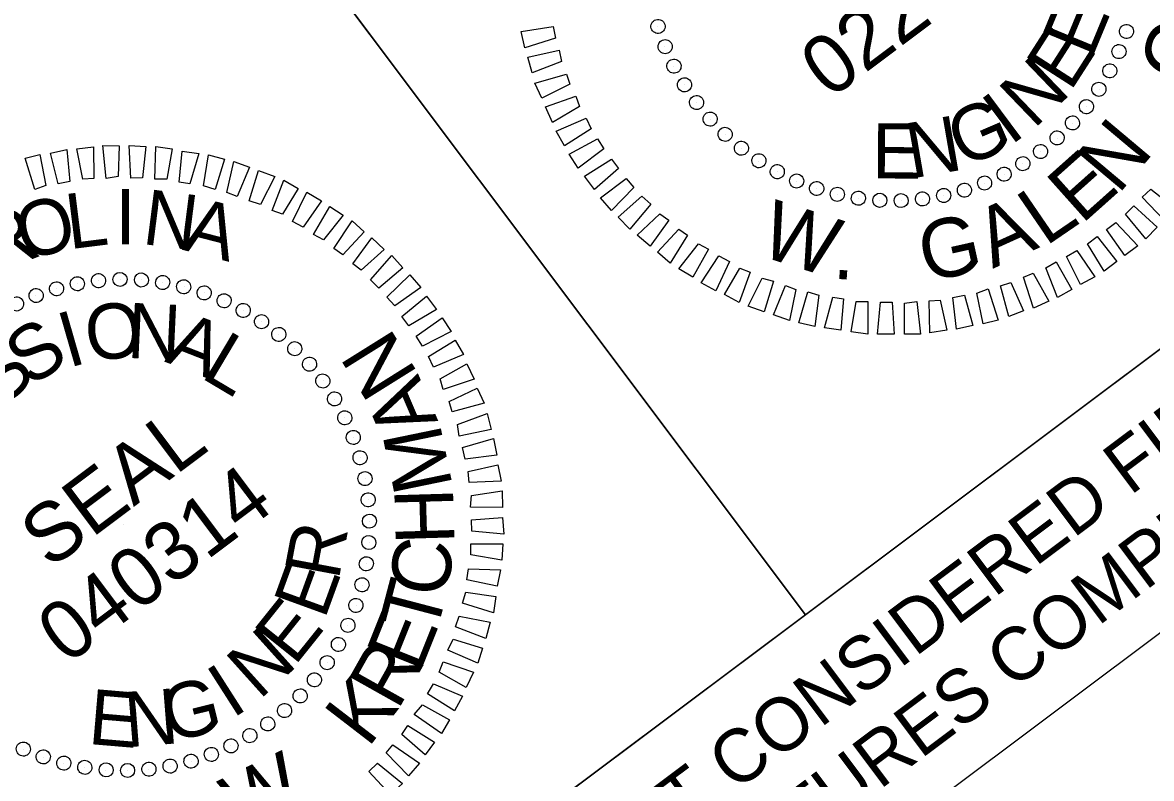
# Model space of a CAD drawing. Extents: x 2186558 to 2188589, y 629855 to 631741.
# Drawn here: x 2187861 to 2187977.7, y 631515.8 to 631594 of the extents above; entities that cross this region are included whole.
import ezdxf

# ---------------------------------------------------------------- set-up
doc = ezdxf.new("R2010")
doc.units = 0
for name, color, linetype in [('Default', 7, 'Continuous'), ('Sheet PE Seal Cell', 7, 'Continuous'), ('Sheet Plan CELL', 7, 'Continuous'), ('Sheet Sticker Exception Certification CELL', 7, 'Continuous')]:
    doc.layers.add(name, color=color, linetype=linetype)

msp = doc.modelspace()

# ---------------------------------------------------------------- linework, layer by layer
at = {"layer": 'Default'}
for p, q in [((2187926.62, 631593.6), (2187926.62, 631593.6)), ((2187975.11, 631593.08), (2187975.11, 631593.08)), ((2187927.37, 631591.5), (2187927.37, 631591.5)), ((2187974.34, 631590.99), (2187974.34, 631590.99)), ((2187928.31, 631589.49), (2187928.31, 631589.49)), ((2187973.37, 631588.99), (2187973.37, 631588.99)), ((2187929.38, 631587.56), (2187929.38, 631587.56)), ((2187972.27, 631587.09), (2187972.27, 631587.09)), ((2187930.63, 631585.72), (2187930.63, 631585.72)), ((2187970.96, 631585.28), (2187970.96, 631585.28)), ((2187932.05, 631584), (2187932.05, 631584)), ((2187969.49, 631583.61), (2187969.49, 631583.61)), ((2187933.6, 631582.44), (2187933.6, 631582.44)), ((2187967.93, 631582.06), (2187967.93, 631582.06)), ((2187935.27, 631580.97), (2187935.27, 631580.97)), ((2187966.21, 631580.65), (2187966.21, 631580.65)), ((2187937.07, 631579.67), (2187937.07, 631579.67)), ((2187938.98, 631578.56), (2187938.98, 631578.56)), ((2187962.45, 631578.33), (2187962.45, 631578.33)), ((2187964.37, 631579.39), (2187964.37, 631579.39)), ((2187940.97, 631577.59), (2187940.97, 631577.59)), ((2187960.43, 631577.38), (2187960.43, 631577.38)), ((2187943.07, 631576.82), (2187943.07, 631576.82)), ((2187945.18, 631576.2), (2187945.18, 631576.2)), ((2187956.2, 631576.11), (2187956.2, 631576.11)), ((2187958.34, 631576.63), (2187958.34, 631576.63)), ((2187947.37, 631575.81), (2187947.37, 631575.81)), ((2187949.58, 631575.57), (2187949.58, 631575.57)), ((2187951.79, 631575.58), (2187951.79, 631575.58)), ((2187954.01, 631575.73), (2187954.01, 631575.73))]:
    msp.add_line(p, q, dxfattribs=at)
for points in [[(2187916.07, 631592.39), (2187912.89, 631591.4), (2187912.52, 631593.08), (2187915.81, 631593.58)], [(2187916.67, 631589.99), (2187913.64, 631588.79), (2187913.19, 631590.41), (2187916.44, 631591.14)], [(2187917.56, 631587.62), (2187914.64, 631586.19), (2187913.92, 631587.74), (2187917.21, 631588.68)], [(2187918.53, 631585.31), (2187915.77, 631583.68), (2187915.02, 631585.27), (2187918.18, 631586.38)], [(2187919.76, 631583), (2187917.01, 631581.26), (2187916.14, 631582.76), (2187919.23, 631584.13)], [(2187921.05, 631580.94), (2187918.42, 631578.96), (2187917.47, 631580.4), (2187920.41, 631581.97)], [(2187922.57, 631578.92), (2187920.09, 631576.74), (2187919.06, 631578.11), (2187921.84, 631579.89)], [(2187924.17, 631576.95), (2187921.85, 631574.57), (2187920.73, 631575.89), (2187923.36, 631577.86)], [(2187925.92, 631575.22), (2187923.74, 631572.64), (2187922.54, 631573.89), (2187924.98, 631576.04)], [(2187977.59, 631576.78), (2187980.2, 631574.75), (2187978.98, 631573.58), (2187976.71, 631575.93)], [(2187975.86, 631575.04), (2187978.26, 631572.85), (2187977.08, 631571.65), (2187974.98, 631574.19)], [(2187927.78, 631573.58), (2187925.84, 631570.86), (2187924.52, 631572.02), (2187926.86, 631574.22)], [(2187929.72, 631572), (2187927.9, 631569.12), (2187926.62, 631570.24), (2187928.8, 631572.64)], [(2187973.99, 631573.32), (2187976.25, 631570.9), (2187974.91, 631569.9), (2187973.02, 631572.59)], [(2187972.05, 631571.86), (2187974.1, 631569.29), (2187972.77, 631568.29), (2187971.07, 631571.13)], [(2187931.87, 631570.57), (2187930.26, 631567.66), (2187928.83, 631568.55), (2187930.83, 631571.12)], [(2187969.96, 631570.42), (2187971.81, 631567.7), (2187970.33, 631566.9), (2187968.9, 631569.81)], [(2187934.04, 631569.29), (2187932.63, 631566.27), (2187931.12, 631567.1), (2187932.96, 631569.88)], [(2187967.8, 631569.25), (2187969.42, 631566.41), (2187967.97, 631565.57), (2187966.74, 631568.64)], [(2187936.19, 631568.19), (2187935.06, 631565.06), (2187933.55, 631565.89), (2187935.13, 631568.59)], [(2187965.44, 631568.1), (2187967.05, 631565.2), (2187965.46, 631564.45), (2187964.43, 631567.67)], [(2187938.59, 631567.26), (2187937.63, 631564.08), (2187935.98, 631564.67), (2187937.41, 631567.58)], [(2187940.89, 631566.39), (2187940.26, 631563.19), (2187938.6, 631563.79), (2187939.83, 631566.8)], [(2187963.13, 631567.13), (2187964.44, 631564.19), (2187962.92, 631563.62), (2187962.06, 631566.77)], [(2187943.3, 631565.8), (2187942.88, 631562.57), (2187941.2, 631562.95), (2187942.16, 631566.14)], [(2187945.85, 631565.43), (2187945.57, 631562.18), (2187943.87, 631562.43), (2187944.72, 631565.6)], [(2187958.35, 631565.82), (2187959.2, 631562.66), (2187957.52, 631562.29), (2187957.15, 631565.56)], [(2187960.79, 631566.45), (2187961.81, 631563.23), (2187960.27, 631562.83), (2187959.6, 631566)], [(2187948.34, 631565.15), (2187948.34, 631561.79), (2187946.63, 631562.03), (2187947.15, 631565.14)], [(2187950.87, 631565.08), (2187951.08, 631561.76), (2187949.35, 631561.79), (2187949.67, 631565.07)], [(2187953.41, 631565.15), (2187953.79, 631561.77), (2187952.13, 631561.79), (2187952.15, 631564.97)], [(2187955.82, 631565.31), (2187956.53, 631562.18), (2187954.75, 631561.92), (2187954.68, 631565.22)]]:
    msp.add_lwpolyline(points, close=True, dxfattribs=at)
for centre, major_axis in [((2187926.66, 631593.6), (-0.698, -0.212)), ((2187975.09, 631593.08), (0.693, -0.227)), ((2187927.4, 631591.51), (-0.676, -0.272)), ((2187974.31, 631591), (0.67, -0.286)), ((2187928.31, 631589.49), (-0.65, -0.33)), ((2187973.36, 631589.01), (0.643, -0.344)), ((2187929.4, 631587.56), (-0.619, -0.385)), ((2187972.23, 631587.1), (0.611, -0.398)), ((2187930.65, 631585.73), (-0.583, -0.438)), ((2187970.94, 631585.3), (0.574, -0.45)), ((2187932.05, 631584.02), (-0.543, -0.487)), ((2187969.5, 631583.62), (0.532, -0.498)), ((2187933.6, 631582.44), (-0.498, -0.532)), ((2187935.28, 631581), (-0.45, -0.574)), ((2187967.91, 631582.07), (0.487, -0.543)), ((2187966.2, 631580.66), (0.438, -0.583)), ((2187937.09, 631579.71), (-0.398, -0.611)), ((2187964.37, 631579.41), (0.385, -0.619)), ((2187938.99, 631578.58), (-0.344, -0.643)), ((2187940.99, 631577.62), (-0.286, -0.67)), ((2187962.44, 631578.32), (0.33, -0.65)), ((2187943.06, 631576.84), (-0.227, -0.693)), ((2187958.33, 631576.67), (0.212, -0.698)), ((2187960.42, 631577.41), (0.272, -0.676)), ((2187945.2, 631576.24), (-0.165, -0.71)), ((2187947.37, 631575.83), (-0.103, -0.722)), ((2187949.58, 631575.62), (-0.04, -0.728)), ((2187951.79, 631575.59), (0.024, -0.729)), ((2187954, 631575.76), (0.087, -0.724)), ((2187956.19, 631576.12), (0.15, -0.713))]:
    msp.add_ellipse(centre, major_axis=major_axis, ratio=0.999708, dxfattribs=at)
at = {"layer": 'Sheet PE Seal Cell'}
for p, q in [((2187866.64, 631567), (2187866.64, 631567)), ((2187868.83, 631567.37), (2187868.83, 631567.37)), ((2187871.05, 631567.45), (2187871.05, 631567.45)), ((2187873.28, 631567.42), (2187873.28, 631567.42)), ((2187875.45, 631567.15), (2187875.45, 631567.15)), ((2187877.67, 631566.73), (2187877.67, 631566.73)), ((2187862.35, 631565.8), (2187862.35, 631565.8)), ((2187864.48, 631566.51), (2187864.48, 631566.51)), ((2187879.74, 631566.07), (2187879.74, 631566.07)), ((2187881.83, 631565.23), (2187881.83, 631565.23)), ((2187883.82, 631564.26), (2187883.82, 631564.26)), ((2187885.69, 631563.12), (2187885.69, 631563.12)), ((2187887.45, 631561.79), (2187887.45, 631561.79)), ((2187889.11, 631560.25), (2187889.11, 631560.25)), ((2187890.66, 631558.69), (2187890.66, 631558.69)), ((2187892.04, 631556.94), (2187892.04, 631556.94)), ((2187893.25, 631555.06), (2187893.25, 631555.06)), ((2187894.28, 631553.11), (2187894.28, 631553.11)), ((2187895.19, 631551.14), (2187895.19, 631551.14)), ((2187895.9, 631549.01), (2187895.9, 631549.01)), ((2187896.38, 631546.84), (2187896.38, 631546.84)), ((2187896.76, 631544.66), (2187896.76, 631544.66)), ((2187896.84, 631542.44), (2187896.84, 631542.44)), ((2187871.44, 631542.05), (2187871.44, 631542.05)), ((2187896.81, 631540.2), (2187896.81, 631540.2)), ((2187896.54, 631538.04), (2187896.54, 631538.04)), ((2187896.11, 631535.82), (2187896.11, 631535.82)), ((2187895.45, 631533.74), (2187895.45, 631533.74)), ((2187894.61, 631531.66), (2187894.61, 631531.66)), ((2187893.64, 631529.66), (2187893.64, 631529.66)), ((2187892.51, 631527.8), (2187892.51, 631527.8)), ((2187891.17, 631526.04), (2187891.17, 631526.04)), ((2187889.64, 631524.37), (2187889.64, 631524.37)), ((2187888.08, 631522.83), (2187888.08, 631522.83)), ((2187886.32, 631521.45), (2187886.32, 631521.45)), ((2187884.45, 631520.23), (2187884.45, 631520.23)), ((2187861.04, 631518.87), (2187861.04, 631518.87)), ((2187882.5, 631519.21), (2187882.5, 631519.21)), ((2187863.13, 631518.03), (2187863.13, 631518.03)), ((2187880.52, 631518.3), (2187880.52, 631518.3)), ((2187865.21, 631517.37), (2187865.21, 631517.37)), ((2187867.42, 631516.95), (2187867.42, 631516.95)), ((2187869.59, 631516.68), (2187869.59, 631516.68)), ((2187871.83, 631516.65), (2187871.83, 631516.65)), ((2187874.04, 631516.73), (2187874.04, 631516.73)), ((2187876.23, 631517.1), (2187876.23, 631517.1)), ((2187878.4, 631517.59), (2187878.4, 631517.59))]:
    msp.add_line(p, q, dxfattribs=at)
for points in [[(2187864.64, 631577.33), (2187863.86, 631580.48), (2187865.55, 631580.86), (2187865.87, 631577.56)], [(2187867.21, 631577.8), (2187866.57, 631580.93), (2187868.3, 631581.15), (2187868.34, 631577.89)], [(2187869.61, 631577.89), (2187869.26, 631581.3), (2187870.95, 631581.24), (2187870.86, 631578.07)], [(2187872.18, 631577.92), (2187872, 631581.27), (2187873.73, 631581.17), (2187873.37, 631577.93)], [(2187874.66, 631577.82), (2187874.74, 631581.17), (2187876.44, 631580.93), (2187875.88, 631577.79)], [(2187877.18, 631577.5), (2187877.49, 631580.71), (2187879.19, 631580.47), (2187878.27, 631577.31)], [(2187862.25, 631576.74), (2187861.26, 631579.99), (2187862.76, 631580.35), (2187863.39, 631577.15)], [(2187879.69, 631577.1), (2187880.19, 631580.32), (2187881.86, 631579.87), (2187880.87, 631576.72)], [(2187882.09, 631576.44), (2187882.8, 631579.63), (2187884.45, 631579.03), (2187883.15, 631576.03)], [(2187884.39, 631575.57), (2187885.38, 631578.71), (2187887.06, 631578.08), (2187885.56, 631575.18)], [(2187886.78, 631574.57), (2187887.98, 631577.69), (2187889.45, 631576.83), (2187887.84, 631574.17)], [(2187888.89, 631573.44), (2187890.37, 631576.45), (2187891.87, 631575.55), (2187889.97, 631572.85)], [(2187891.05, 631572.08), (2187892.73, 631574.99), (2187894.12, 631574.07), (2187892.09, 631571.54)], [(2187893.16, 631570.63), (2187895.05, 631573.5), (2187896.3, 631572.35), (2187894.08, 631569.99)], [(2187895.1, 631569.05), (2187897.08, 631571.73), (2187898.35, 631570.54), (2187895.98, 631568.38)], [(2187896.93, 631567.38), (2187899.13, 631569.92), (2187900.29, 631568.63), (2187897.82, 631566.53)], [(2187898.63, 631565.62), (2187901.02, 631567.92), (2187902.13, 631566.6), (2187899.44, 631564.71)], [(2187900.19, 631563.62), (2187902.73, 631565.72), (2187903.76, 631564.34), (2187900.92, 631562.65)], [(2187901.67, 631561.57), (2187904.36, 631563.46), (2187905.28, 631562.06), (2187902.31, 631560.53)], [(2187902.92, 631559.47), (2187905.7, 631561.17), (2187906.57, 631559.67), (2187903.45, 631558.35)], [(2187904.15, 631557.16), (2187906.9, 631558.72), (2187907.65, 631557.13), (2187904.46, 631556.07)], [(2187905.08, 631554.82), (2187907.98, 631556.18), (2187908.7, 631554.63), (2187905.39, 631553.73)], [(2187905.93, 631552.42), (2187908.99, 631553.58), (2187909.4, 631551.93), (2187906.12, 631551.24)], [(2187906.46, 631550.04), (2187909.67, 631550.99), (2187910, 631549.28), (2187906.72, 631548.84)], [(2187907.04, 631547.57), (2187910.11, 631548.28), (2187910.45, 631546.57), (2187907.14, 631546.43)], [(2187907.38, 631545.09), (2187910.56, 631545.58), (2187910.6, 631543.84), (2187907.28, 631543.88)], [(2187907.38, 631542.56), (2187910.6, 631542.83), (2187910.71, 631541.08), (2187907.43, 631541.4)], [(2187907.32, 631540.11), (2187910.61, 631540.11), (2187910.51, 631538.39), (2187907.3, 631538.96)], [(2187907.06, 631537.51), (2187910.37, 631537.4), (2187910.05, 631535.71), (2187906.9, 631536.38)], [(2187906.78, 631535.09), (2187909.9, 631534.65), (2187909.66, 631532.95), (2187906.44, 631533.95)], [(2187906.11, 631532.62), (2187909.31, 631531.98), (2187908.85, 631530.31), (2187905.73, 631531.52)], [(2187905.48, 631530.25), (2187908.53, 631529.31), (2187908.05, 631527.75), (2187904.95, 631529.1)], [(2187904.46, 631527.9), (2187907.6, 631526.84), (2187906.83, 631525.25), (2187904.05, 631526.84)], [(2187903.45, 631525.62), (2187906.44, 631524.33), (2187905.61, 631522.82), (2187902.83, 631524.59)], [(2187902.3, 631523.44), (2187905.12, 631521.88), (2187904.27, 631520.48), (2187901.47, 631522.43)], [(2187900.8, 631521.3), (2187903.56, 631519.57), (2187902.58, 631518.26), (2187900.17, 631520.38)], [(2187899.25, 631519.31), (2187902.02, 631517.4), (2187900.86, 631516.09), (2187898.56, 631518.47)], [(2187897.65, 631517.41), (2187900.24, 631515.31), (2187898.99, 631514.18), (2187896.76, 631516.56)]]:
    msp.add_lwpolyline(points, close=True, dxfattribs=at)
for centre, major_axis in [((2187866.64, 631566.99), (-0.138, 0.716)), ((2187868.83, 631567.31), (-0.075, 0.725)), ((2187871.05, 631567.44), (-0.011, 0.729)), ((2187873.26, 631567.38), (0.052, 0.727)), ((2187875.46, 631567.12), (0.116, 0.72)), ((2187864.49, 631566.47), (-0.2, 0.701)), ((2187877.63, 631566.68), (0.178, 0.707)), ((2187879.75, 631566.04), (0.239, 0.689)), ((2187860.35, 631564.9), (-0.318, 0.656)), ((2187862.38, 631565.77), (-0.26, 0.681)), ((2187881.81, 631565.23), (0.298, 0.665)), ((2187883.79, 631564.23), (0.355, 0.637)), ((2187885.68, 631563.07), (0.409, 0.604)), ((2187887.46, 631561.75), (0.46, 0.566)), ((2187889.11, 631560.28), (0.507, 0.523)), ((2187890.64, 631558.67), (0.551, 0.477)), ((2187892.01, 631556.93), (0.591, 0.427)), ((2187893.23, 631555.08), (0.626, 0.374)), ((2187894.28, 631553.13), (0.656, 0.318)), ((2187895.16, 631551.1), (0.681, 0.26)), ((2187895.86, 631549), (0.701, 0.2)), ((2187896.37, 631546.84), (0.716, 0.138)), ((2187896.7, 631544.65), (0.725, 0.075)), ((2187896.83, 631542.44), (0.729, 0.011)), ((2187896.76, 631540.23), (0.727, -0.052)), ((2187896.51, 631538.03), (0.72, -0.116)), ((2187896.06, 631535.86), (0.707, -0.178)), ((2187895.43, 631533.73), (0.689, -0.239)), ((2187894.61, 631531.67), (0.665, -0.298)), ((2187893.62, 631529.69), (0.637, -0.355)), ((2187892.46, 631527.81), (0.604, -0.409)), ((2187891.14, 631526.03), (0.566, -0.46)), ((2187889.67, 631524.37), (0.523, -0.507)), ((2187888.06, 631522.85), (0.477, -0.551)), ((2187886.32, 631521.47), (0.427, -0.591)), ((2187882.52, 631519.2), (0.318, -0.656)), ((2187884.47, 631520.26), (0.374, -0.626)), ((2187861.06, 631518.87), (-0.298, -0.665)), ((2187863.12, 631518.06), (-0.239, -0.689)), ((2187880.49, 631518.32), (0.26, -0.681)), ((2187865.24, 631517.42), (-0.178, -0.707)), ((2187867.41, 631516.98), (-0.116, -0.72)), ((2187876.23, 631517.11), (0.138, -0.716)), ((2187878.39, 631517.62), (0.2, -0.701)), ((2187869.61, 631516.72), (-0.052, -0.727)), ((2187871.83, 631516.66), (0.011, -0.729)), ((2187874.04, 631516.79), (0.075, -0.725))]:
    msp.add_ellipse(centre, major_axis=major_axis, ratio=0.999708, dxfattribs=at)
at = {"layer": 'Sheet Plan CELL'}
msp.add_line((2187874.4, 631622.77), (2187941.88, 631532.8), dxfattribs=at)
for points in [[(2187874.4, 631622.77), (2187954.4, 631682.76), (2188021.9, 631592.74), (2187941.9, 631532.75)], [(2187794.35, 631562.75), (2187874.4, 631622.77), (2187941.9, 631532.75), (2187861.84, 631472.76)], [(2187361.55, 629972.91), (2186731.7, 630812.99), (2187771.81, 631592.82), (2187861.84, 631472.76), (2188021.9, 631592.74), (2188561.73, 630872.69)]]:
    msp.add_lwpolyline(points, close=True, dxfattribs=at)
at = {"layer": 'Sheet Sticker Exception Certification CELL'}
for p, q in [((2187861.84, 631472.76), (2188021.89, 631592.75)), ((2187861.84, 631472.76), (2188021.89, 631592.75)), ((2188035.99, 631573.95), (2187875.94, 631453.96)), ((2188035.99, 631573.95), (2187875.94, 631453.96))]:
    msp.add_line(p, q, dxfattribs=at)

# ---------------------------------------------------------------- texts
at = {"layer": 'Default'}
for s, height, rotation, p in [('022000', 6.075, 36.8829, (2187944.42, 631586)), ('E', 5.71, 67.501, (2187971.51, 631590.24)), ('E', 5.71, 57.3041, (2187969.28, 631586.77)), ('C', 6.07, 73.1407, (2187982.13, 631587.31)), ('N', 5.71, 43.9013, (2187965.49, 631582.91)), ('I', 5.71, 36.6363, (2187963.09, 631581.22)), ('G', 5.71, 23.2336, (2187958.18, 631578.94)), ('N', 5.71, 9.8308, (2187952.88, 631577.87)), ('E', 5.71, 359.6339, (2187948.76, 631577.89)), ('N', 6.07, 49.9519, (2187974.23, 631576.14)), ('E', 6.07, 41.7438, (2187970.45, 631573.07)), ('L', 6.07, 34.3784, (2187966.71, 631570.8)), ('W', 6.07, 342.4456, (2187936.92, 631569.97)), ('A', 6.07, 24.4225, (2187961.26, 631568.53)), ('G', 6.07, 12.5629, (2187954.37, 631567.11)), ('.', 6.07, 356.131, (2187944.65, 631567.53))]:
    msp.add_text(s, height=height, rotation=rotation, dxfattribs=at).set_placement(p)
at = {"layer": 'Sheet PE Seal Cell'}
for s, height, rotation, p in [('L', 5.71, 7.1038, (2187865.81, 631570.55)), ('I', 5.71, 359.9031, (2187870.55, 631571.07)), ('N', 5.71, 352.7018, (2187873.23, 631571.12)), ('O', 5.71, 14.3041, (2187861.12, 631569.37)), ('A', 5.71, 345.5001, (2187877.41, 631570.52)), ('R', 5.71, 21.504, (2187857.95, 631567.95)), ('O', 5.71, 6.7164, (2187867.77, 631558.92)), ('N', 5.71, 357.3595, (2187871.7, 631559.33)), ('I', 5.71, 16.0725, (2187865.72, 631558.27)), ('A', 5.71, 338.6432, (2187875.58, 631558.96)), ('S', 5.71, 34.7833, (2187861.81, 631556.22)), ('L', 5.71, 329.2838, (2187879.26, 631557.35)), ('N', 6.07, 122.0173, (2187901.93, 631557.65)), ('S', 5.71, 44.1385, (2187858.93, 631553.99)), ('A', 6.07, 113.1769, (2187903.96, 631552.78)), ('SEAL', 6.073, 36.8829, (2187863.79, 631537.39)), ('M', 6.07, 101.6475, (2187905.45, 631546.06)), ('040314', 6.073, 36.8829, (2187865.55, 631527.5)), ('H', 6.07, 91.6635, (2187905.63, 631540.1)), ('R', 5.71, 79.3643, (2187893.64, 631536.24)), ('C', 6.07, 82.0813, (2187904.83, 631534.44)), ('E', 5.71, 70.007, (2187892.19, 631532.18)), ('T', 6.07, 75.2811, (2187903.69, 631530.54)), ('E', 5.71, 51.2947, (2187889.09, 631527.38)), ('E', 6.07, 68.1717, (2187902.02, 631526.63)), ('N', 5.71, 41.9393, (2187885.44, 631523.89)), ('R', 6.07, 60.6915, (2187899.75, 631522.78)), ('I', 5.71, 32.5841, (2187882.64, 631521.97)), ('G', 5.71, 13.8732, (2187876.18, 631519.53)), ('K', 6.07, 52.4076, (2187896.68, 631518.9)), ('E', 5.71, 355.1598, (2187867.66, 631519.41)), ('N', 5.71, 4.5169, (2187871.74, 631519.05)), ('W', 6.07, 25.6394, (2187883.55, 631510.01))]:
    msp.add_text(s, height=height, rotation=rotation, dxfattribs=at).set_placement(p)
at = {"layer": 'Sheet Plan CELL'}
msp.add_text('ROADWAY DESIGN', height=5.0001, rotation=36.8593, dxfattribs=at).set_placement((2187814.23, 631568.54))
at = {"layer": 'Sheet Sticker Exception Certification CELL'}
for s, p in [('DOCUMENT NOT CONSIDERED FINAL', (2187884.9, 631477.12)), ('DOCUMENT NOT CONSIDERED FINAL', (2187884.9, 631477.12)), ('UNLESS ALL SIGNATURES COMPLETED', (2187886.12, 631467.04)), ('UNLESS ALL SIGNATURES COMPLETED', (2187886.12, 631467.04))]:
    msp.add_text(s, height=5.5, rotation=36.8593, dxfattribs=at).set_placement(p)

doc.saveas('drawing.dxf')
